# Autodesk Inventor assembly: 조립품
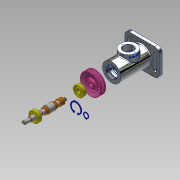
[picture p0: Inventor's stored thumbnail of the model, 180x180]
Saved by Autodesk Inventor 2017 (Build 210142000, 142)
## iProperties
Part Number: 조립품
Material: 일반
Document SubType Name: Assembly
Designer: user
Author: user
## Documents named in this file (10)
- C:\Users\user\Desktop\710706V1029_정익수\조립품.iam
- C:\Users\user\Desktop\710706V1029_정익수\본체.ipt
- C:\Users\user\Desktop\710706V1029\V-벨트풀리.ipt
- C:\Users\user\Desktop\710706V1029\키 4 x 4 x 18.ipt
- C:\Users\user\Desktop\710706V1029\축.ipt
- C:\Users\user\Desktop\710706V1029\베어링 15 x 35 x 11.ipt
- C:\Users\user\Desktop\710706V1029\부시1.ipt
- C:\Users\user\Desktop\710706V1029\부시2.ipt
- C:\Users\user\Desktop\710706V1029\멈춤링 15 x 1.ipt
- C:\Users\user\Desktop\710706V1029\멈춤링 35 x 1.6.ipt
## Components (1 placed, 1 different names)
1. V-벨트풀리:1
